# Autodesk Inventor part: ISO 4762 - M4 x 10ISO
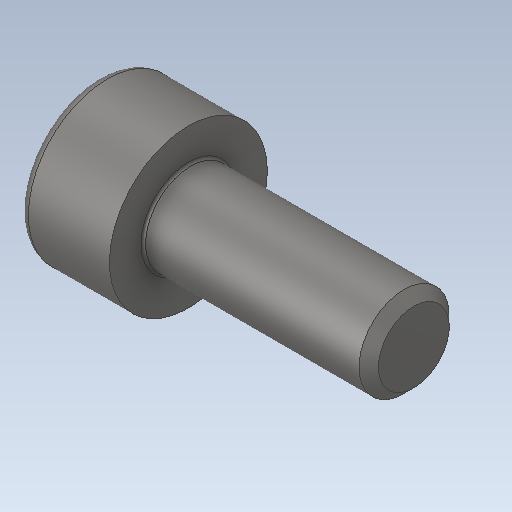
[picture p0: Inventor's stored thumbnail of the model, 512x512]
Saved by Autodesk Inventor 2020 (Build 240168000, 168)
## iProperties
Created: 2015-11
Part Number: ISO 4762 - M4 x 10ISO
Material: Ogólny
Document SubType Name: Modeling
Designer: Tomasz
Density: 1 g/cm^3
Appearance: Domyślna
Sending System: SolidWorks 2017
Last Author: Tomasz
Last Saved: 2017-10-01
Author: Tomasz
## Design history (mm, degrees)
feature "Imported1"
node "Bryła1"
